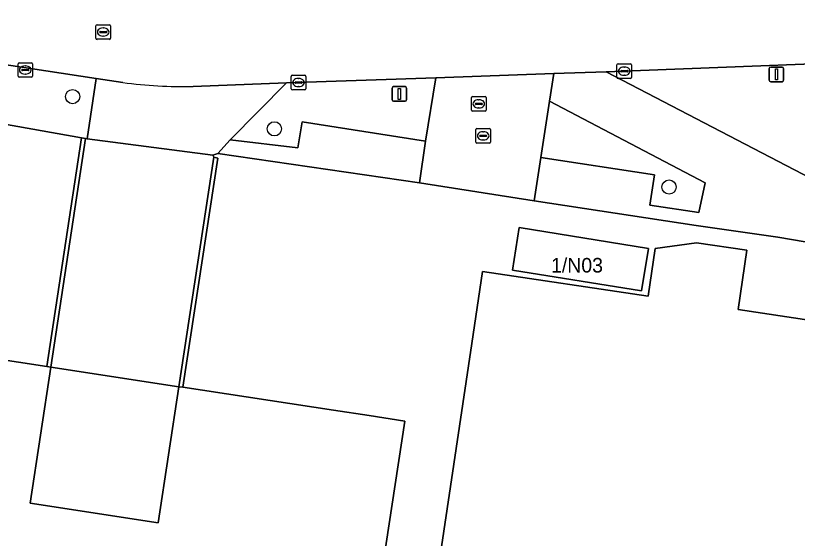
# Model space of a CAD drawing. Extents: x 163008 to 163854, y 382777 to 383982.
# Drawn here: x 163610.4 to 163664.1, y 382929.1 to 382965 of the extents above; entities that cross this region are included whole.
import ezdxf

# ---------------------------------------------------------------- set-up
doc = ezdxf.new("R2010")
doc.units = 0
for name, color, linetype in [('IMGEO_Berm_groen', 7, 'Continuous'), ('IMGEO_Boom', 7, 'Continuous'), ('IMGEO_Erf', 7, 'Continuous'), ('IMGEO_Groenvoorziening', 7, 'Continuous'), ('IMGEO_Kolk', 7, 'Continuous'), ('IMGEO_Lichtmast', 7, 'Continuous'), ('IMGEO_Muur', 7, 'Continuous'), ('IMGEO_Pand', 7, 'Continuous'), ('IMGEO_Pand_nummerreeks', 7, 'Continuous'), ('IMGEO_Pand_overbouw', 7, 'Continuous'), ('IMGEO_Rijbaan_lokaal_gesloten', 7, 'Continuous'), ('IMGEO_Rioolput', 7, 'Continuous'), ('IMGEO_Verkeersbordpaal', 7, 'Continuous'), ('IMGEO_Voetpad_open', 7, 'Continuous')]:
    doc.layers.add(name, color=color, linetype=linetype)

msp = doc.modelspace()

# ---------------------------------------------------------------- linework, layer by layer
at = {"layer": 'IMGEO_Berm_groen'}
msp.add_lwpolyline([(163639.301, 382960.692), (163629.051, 382960.332), (163625.178, 382956.437), (163629.814, 382955.872), (163630.123, 382957.675), (163638.596, 382956.331)], close=True, dxfattribs=at)
at = {"layer": 'IMGEO_Boom'}
for centre in [(163614.344, 382959.396), (163628.209, 382957.187), (163655.326, 382953.186)]:
    msp.add_circle(centre, 0.489, dxfattribs=at)
at = {"layer": 'IMGEO_Erf'}
for points in [[(163582.963, 382945.196), (163591.206, 382943.949), (163590.876, 382941.687), (163596.466, 382940.9), (163596.75, 382942.917), (163596.12, 382943.015), (163596.147, 382943.182), (163596.173, 382943.346), (163599.763, 382942.813), (163602.213, 382942.44), (163612.574, 382940.867), (163614.959, 382956.568), (163598.719, 382959.447), (163593.467, 382960.242), (163569.919, 382963.81)], [(163675.95, 382947.517), (163662.801, 382949.742), (163657.187, 382950.546), (163646.06, 382952.245), (163638.173, 382953.479), (163624.316, 382955.496), (163623.99, 382955.385), (163624.04, 382955.237), (163624.315, 382955.169), (163621.912, 382939.445), (163632.279, 382937.867), (163634.71, 382937.499), (163637.177, 382937.125), (163630.658, 382894.541)], [(163633.371, 382886.155), (163641.775, 382942.458), (163642.513, 382947.403), (163653.887, 382945.706), (163654.375, 382948.97), (163657.213, 382949.356), (163660.676, 382948.848), (163660.069, 382944.782), (163665.094, 382944.032)]]:
    msp.add_lwpolyline(points, dxfattribs=at)
msp.add_lwpolyline([(163653.443, 382946.065), (163644.566, 382947.492), (163645.035, 382950.407), (163653.912, 382948.979)], close=True, dxfattribs=at)
at = {"layer": 'IMGEO_Groenvoorziening'}
msp.add_lwpolyline([(163674.627, 382962.016), (163650.997, 382961.099), (163669.011, 382951.747), (163679.228, 382950.224)], dxfattribs=at)
msp.add_lwpolyline([(163647.115, 382959.08), (163646.511, 382955.211), (163654.325, 382954.019), (163654.013, 382951.942), (163657.373, 382951.433), (163657.804, 382953.488)], close=True, dxfattribs=at)
at = {"layer": 'IMGEO_Kolk'}
for p, q in [((163610.593, 382960.798), (163610.593, 382961.65)), ((163610.668, 382961.724), (163611.52, 382961.724)), ((163610.852, 382961.218), (163610.852, 382961.23)), ((163610.895, 382961.267), (163611.293, 382961.267)), ((163611.081, 382961.504), (163611.106, 382961.504)), ((163611.336, 382961.23), (163611.336, 382961.218)), ((163611.594, 382961.65), (163611.594, 382960.798)), ((163651.747, 382960.717), (163651.747, 382961.569)), ((163651.822, 382961.643), (163652.674, 382961.643)), ((163652.235, 382961.423), (163652.26, 382961.423)), ((163652.748, 382961.569), (163652.748, 382960.717)), ((163611.52, 382960.724), (163610.668, 382960.724)), ((163611.29, 382961.181), (163610.892, 382961.181)), ((163611.104, 382960.944), (163611.079, 382960.944)), ((163629.369, 382959.937), (163629.369, 382960.789)), ((163629.444, 382960.863), (163630.296, 382960.863)), ((163630.37, 382960.789), (163630.37, 382959.937)), ((163652.006, 382961.137), (163652.006, 382961.149)), ((163652.444, 382961.1), (163652.046, 382961.1)), ((163652.049, 382961.186), (163652.447, 382961.186)), ((163652.258, 382960.863), (163652.233, 382960.863)), ((163652.49, 382961.149), (163652.49, 382961.137)), ((163629.628, 382960.357), (163629.628, 382960.369)), ((163630.066, 382960.32), (163629.668, 382960.32)), ((163629.671, 382960.406), (163630.069, 382960.406)), ((163629.857, 382960.643), (163629.882, 382960.643)), ((163630.112, 382960.369), (163630.112, 382960.357)), ((163652.674, 382960.643), (163651.822, 382960.643)), ((163630.296, 382959.863), (163629.444, 382959.863)), ((163629.88, 382960.083), (163629.855, 382960.083)), ((163642.053, 382956.279), (163642.053, 382957.131)), ((163642.128, 382957.205), (163642.98, 382957.205)), ((163642.541, 382956.985), (163642.566, 382956.985)), ((163643.054, 382957.131), (163643.054, 382956.279)), ((163642.312, 382956.699), (163642.312, 382956.711)), ((163642.75, 382956.662), (163642.352, 382956.662)), ((163642.355, 382956.748), (163642.753, 382956.748)), ((163642.564, 382956.425), (163642.539, 382956.425)), ((163642.796, 382956.711), (163642.796, 382956.699)), ((163642.98, 382956.205), (163642.128, 382956.205))]:
    msp.add_line(p, q, dxfattribs=at)
for points in [[(163610.593, 382960.798), (163610.593, 382961.65)], [(163610.668, 382961.724), (163611.52, 382961.724)], [(163611.594, 382961.65), (163611.594, 382960.798)], [(163651.747, 382960.717), (163651.747, 382961.569)], [(163651.822, 382961.643), (163652.674, 382961.643)], [(163652.748, 382961.569), (163652.748, 382960.717)], [(163611.52, 382960.724), (163610.668, 382960.724)], [(163629.369, 382959.937), (163629.369, 382960.789)], [(163629.444, 382960.863), (163630.296, 382960.863)], [(163630.37, 382960.789), (163630.37, 382959.937)], [(163652.674, 382960.643), (163651.822, 382960.643)], [(163630.296, 382959.863), (163629.444, 382959.863)], [(163642.053, 382956.279), (163642.053, 382957.131)], [(163642.128, 382957.205), (163642.98, 382957.205)], [(163643.054, 382957.131), (163643.054, 382956.279)], [(163642.98, 382956.205), (163642.128, 382956.205)]]:
    msp.add_lwpolyline(points, dxfattribs=at)
for centre, radius, start, end in [((163610.67, 382961.648), 0.0765, 91.552, 178.448), ((163610.67, 382961.648), 0.0765, 91.552, 178.448), ((163610.892, 382961.227), 0.0403, 85.8775, 175.7526), ((163610.889, 382961.217), 0.0366, 178.938, 274.7102), ((163611.293, 382961.224), 0.043, 264.8664, 352.4533), ((163611.297, 382961.229), 0.0386, 1.7309, 96.639), ((163611.518, 382961.648), 0.0765, 1.552, 88.448), ((163611.518, 382961.648), 0.0765, 1.552, 88.448), ((163651.824, 382961.567), 0.0765, 91.552, 178.448), ((163651.824, 382961.567), 0.0765, 91.552, 178.448), ((163652.672, 382961.567), 0.0765, 1.552, 88.448), ((163652.672, 382961.567), 0.0765, 1.552, 88.448), ((163610.67, 382960.8), 0.0765, 181.552, 268.448), ((163610.67, 382960.8), 0.0765, 181.552, 268.448), ((163611.518, 382960.8), 0.0765, 271.552, 358.448), ((163611.518, 382960.8), 0.0765, 271.552, 358.448), ((163629.446, 382960.787), 0.0765, 91.552, 178.448), ((163629.446, 382960.787), 0.0765, 91.552, 178.448), ((163630.294, 382960.787), 0.0765, 1.552, 88.448), ((163630.294, 382960.787), 0.0765, 1.552, 88.448), ((163651.824, 382960.719), 0.0765, 181.552, 268.448), ((163651.824, 382960.719), 0.0765, 181.552, 268.448), ((163652.046, 382961.146), 0.0403, 85.8775, 175.7526), ((163652.043, 382961.136), 0.0366, 178.938, 274.7102), ((163652.447, 382961.143), 0.043, 264.8664, 352.4533), ((163652.451, 382961.148), 0.0386, 1.7309, 96.639), ((163652.672, 382960.719), 0.0765, 271.552, 358.448), ((163652.672, 382960.719), 0.0765, 271.552, 358.448), ((163629.668, 382960.366), 0.0403, 85.8775, 175.7526), ((163629.665, 382960.356), 0.0366, 178.938, 274.7102), ((163630.069, 382960.363), 0.043, 264.8664, 352.4533), ((163630.073, 382960.368), 0.0386, 1.7309, 96.639), ((163629.446, 382959.939), 0.0765, 181.552, 268.448), ((163629.446, 382959.939), 0.0765, 181.552, 268.448), ((163630.294, 382959.939), 0.0765, 271.552, 358.448), ((163630.294, 382959.939), 0.0765, 271.552, 358.448), ((163642.13, 382957.129), 0.0765, 91.552, 178.448), ((163642.13, 382957.129), 0.0765, 91.552, 178.448), ((163642.978, 382957.129), 0.0765, 1.552, 88.448), ((163642.978, 382957.129), 0.0765, 1.552, 88.448), ((163642.352, 382956.708), 0.0403, 85.8775, 175.7526), ((163642.349, 382956.698), 0.0366, 178.938, 274.7102), ((163642.753, 382956.705), 0.043, 264.8664, 352.4533), ((163642.757, 382956.71), 0.0386, 1.7309, 96.639), ((163642.13, 382956.281), 0.0765, 181.552, 268.448), ((163642.13, 382956.281), 0.0765, 181.552, 268.448), ((163642.978, 382956.281), 0.0765, 271.552, 358.448), ((163642.978, 382956.281), 0.0765, 271.552, 358.448)]:
    msp.add_arc(centre, radius, start, end, dxfattribs=at)
for centre, major_axis, ratio, start_param, end_param in [((163611.08, 382961.224), (-0.387, 0.002), 0.722429, 4.712389, 7.853982), ((163611.105, 382961.224), (-0.39, 0.002), 0.717154, 1.570796, 4.712389), ((163652.234, 382961.143), (-0.387, 0.002), 0.722429, 4.712389, 7.853982), ((163652.259, 382961.143), (-0.39, 0.002), 0.717154, 1.570796, 4.712389), ((163629.856, 382960.363), (-0.387, 0.002), 0.722429, 4.712389, 7.853982), ((163629.881, 382960.363), (-0.39, 0.002), 0.717154, 1.570796, 4.712389), ((163642.54, 382956.705), (-0.387, 0.002), 0.722429, 4.712389, 7.853982), ((163642.565, 382956.705), (-0.39, 0.002), 0.717154, 1.570796, 4.712389)]:
    msp.add_ellipse(centre, major_axis=major_axis, ratio=ratio, start_param=start_param, end_param=end_param, dxfattribs=at)
at = {"layer": 'IMGEO_Lichtmast'}
for p, q in [((163662.209, 382960.522), (163662.209, 382961.322)), ((163662.209, 382961.322), (163662.209, 382960.522)), ((163662.309, 382961.422), (163663.099, 382961.422)), ((163663.099, 382961.422), (163662.309, 382961.422)), ((163663.199, 382961.322), (163663.199, 382960.522)), ((163663.199, 382960.522), (163663.199, 382961.322)), ((163663.099, 382960.422), (163662.309, 382960.422)), ((163662.309, 382960.422), (163663.099, 382960.422))]:
    msp.add_line(p, q, dxfattribs=at)
msp.add_lwpolyline([(163662.629, 382961.297), (163662.779, 382961.297), (163662.779, 382960.547), (163662.629, 382960.547), (163662.629, 382961.297)], dxfattribs=at)
for centre, start, end in [((163662.309, 382961.322), 90, 180), ((163662.309, 382961.322), 90, 180), ((163663.099, 382961.322), 0, 90), ((163663.099, 382961.322), 360, 90), ((163662.309, 382960.522), 180, 270), ((163662.309, 382960.522), 180, 270), ((163663.099, 382960.522), 270, 0), ((163663.099, 382960.522), 270, 0)]:
    msp.add_arc(centre, 0.1, start, end, dxfattribs=at)
at = {"layer": 'IMGEO_Muur'}
for points in [[(163614.959, 382956.568), (163612.574, 382940.867), (163612.842, 382940.823), (163615.226, 382956.521)], [(163624.315, 382955.169), (163624.04, 382955.237), (163621.646, 382939.485), (163621.912, 382939.445)]]:
    msp.add_lwpolyline(points, close=True, dxfattribs=at)
at = {"layer": 'IMGEO_Pand'}
msp.add_lwpolyline([(163653.443, 382946.065), (163653.912, 382948.979), (163645.035, 382950.407), (163644.566, 382947.492)], close=True, dxfattribs=at)
for points in [[(163686.07, 382880.075), (163694.944, 382939.641), (163675.573, 382942.478), (163671.874, 382943.02), (163665.094, 382944.032), (163660.069, 382944.782), (163660.676, 382948.848), (163657.213, 382949.356), (163654.375, 382948.97), (163653.887, 382945.706), (163642.513, 382947.403), (163641.775, 382942.458), (163633.371, 382886.155), (163632.813, 382886.325), (163623.367, 382823.699)], [(163630.658, 382894.541), (163637.177, 382937.125), (163634.71, 382937.499), (163632.279, 382937.867), (163621.912, 382939.445), (163621.646, 382939.485), (163620.226, 382930.143), (163611.422, 382931.48), (163612.842, 382940.823), (163612.574, 382940.867), (163602.213, 382942.44), (163599.763, 382942.813), (163596.173, 382943.346), (163596.147, 382943.182), (163596.12, 382943.015), (163596.75, 382942.917), (163596.466, 382940.9), (163590.876, 382941.687), (163591.206, 382943.949), (163582.963, 382945.196)]]:
    msp.add_lwpolyline(points, dxfattribs=at)
at = {"layer": 'IMGEO_Pand_overbouw'}
msp.add_lwpolyline([(163612.842, 382940.823), (163611.422, 382931.48), (163620.226, 382930.143), (163621.646, 382939.485)], close=True, dxfattribs=at)
at = {"layer": 'IMGEO_Rijbaan_lokaal_gesloten'}
for points in [[(163292.545, 383009.569), (163296.84, 383008.817), (163304.96, 383007.61), (163321.045, 383005.203), (163329.509, 383003.951), (163334.952, 383003.075), (163339.568, 383002.444), (163411.931, 382991.584), (163416.286, 382990.97), (163423.758, 382989.792), (163438.655, 382987.556), (163481.173, 382981.103), (163506.122, 382977.311), (163550.446, 382970.596), (163562.809, 382968.717), (163570.543, 382967.542), (163594.132, 382963.957), (163599.415, 382963.154), (163615.953, 382960.64), (163617.8, 382960.359)], [(163622.627, 382960.091), (163629.051, 382960.332), (163639.301, 382960.692), (163647.404, 382960.974), (163650.997, 382961.099), (163674.627, 382962.016), (163676.656, 382962.06)]]:
    msp.add_lwpolyline(points, dxfattribs=at)
for points in [[(163624.04, 382955.237), (163623.99, 382955.385), (163615.342, 382956.5), (163615.226, 382956.521), (163612.842, 382940.823), (163621.646, 382939.485)], [(163612.842, 382940.823), (163611.422, 382931.48), (163620.226, 382930.143), (163621.646, 382939.485)]]:
    msp.add_lwpolyline(points, close=True, dxfattribs=at)
msp.add_arc((163622.092, 382994.054), 33.967, 262.7414, 270.9029, dxfattribs=at)
at = {"layer": 'IMGEO_Rioolput'}
for p, q in [((163615.946, 382963.403), (163615.946, 382964.255)), ((163616.021, 382964.329), (163616.873, 382964.329)), ((163616.434, 382964.109), (163616.459, 382964.109)), ((163616.947, 382964.255), (163616.947, 382963.403)), ((163616.205, 382963.823), (163616.205, 382963.835)), ((163616.643, 382963.786), (163616.245, 382963.786)), ((163616.248, 382963.872), (163616.646, 382963.872)), ((163616.457, 382963.549), (163616.432, 382963.549)), ((163616.689, 382963.835), (163616.689, 382963.823)), ((163616.873, 382963.329), (163616.021, 382963.329)), ((163641.754, 382958.474), (163641.754, 382959.326)), ((163641.829, 382959.4), (163642.681, 382959.4)), ((163642.242, 382959.18), (163642.267, 382959.18)), ((163642.755, 382959.326), (163642.755, 382958.474)), ((163642.013, 382958.894), (163642.013, 382958.906)), ((163642.451, 382958.857), (163642.053, 382958.857)), ((163642.056, 382958.943), (163642.454, 382958.943)), ((163642.265, 382958.62), (163642.24, 382958.62)), ((163642.497, 382958.906), (163642.497, 382958.894)), ((163642.681, 382958.4), (163641.829, 382958.4))]:
    msp.add_line(p, q, dxfattribs=at)
for points in [[(163615.946, 382963.403), (163615.946, 382964.255)], [(163616.021, 382964.329), (163616.873, 382964.329)], [(163616.947, 382964.255), (163616.947, 382963.403)], [(163616.873, 382963.329), (163616.021, 382963.329)], [(163641.754, 382958.474), (163641.754, 382959.326)], [(163641.829, 382959.4), (163642.681, 382959.4)], [(163642.755, 382959.326), (163642.755, 382958.474)], [(163642.681, 382958.4), (163641.829, 382958.4)]]:
    msp.add_lwpolyline(points, dxfattribs=at)
for centre, radius, start, end in [((163616.023, 382964.253), 0.0765, 91.552, 178.448), ((163616.023, 382964.253), 0.0765, 91.552, 178.448), ((163616.871, 382964.253), 0.0765, 1.552, 88.448), ((163616.871, 382964.253), 0.0765, 1.552, 88.448), ((163616.023, 382963.405), 0.0765, 181.552, 268.448), ((163616.023, 382963.405), 0.0765, 181.552, 268.448), ((163616.245, 382963.832), 0.0403, 85.8775, 175.7526), ((163616.242, 382963.822), 0.0366, 178.938, 274.7102), ((163616.646, 382963.829), 0.043, 264.8664, 352.4533), ((163616.65, 382963.834), 0.0386, 1.7309, 96.639), ((163616.871, 382963.405), 0.0765, 271.552, 358.448), ((163616.871, 382963.405), 0.0765, 271.552, 358.448), ((163641.831, 382959.324), 0.0765, 91.552, 178.448), ((163641.831, 382959.324), 0.0765, 91.552, 178.448), ((163642.679, 382959.324), 0.0765, 1.552, 88.448), ((163642.679, 382959.324), 0.0765, 1.552, 88.448), ((163642.053, 382958.903), 0.0403, 85.8775, 175.7526), ((163642.05, 382958.893), 0.0366, 178.938, 274.7102), ((163642.454, 382958.9), 0.043, 264.8664, 352.4533), ((163642.458, 382958.905), 0.0386, 1.7309, 96.639), ((163641.831, 382958.476), 0.0765, 181.552, 268.448), ((163641.831, 382958.476), 0.0765, 181.552, 268.448), ((163642.679, 382958.476), 0.0765, 271.552, 358.448), ((163642.679, 382958.476), 0.0765, 271.552, 358.448)]:
    msp.add_arc(centre, radius, start, end, dxfattribs=at)
for centre, major_axis, ratio, start_param, end_param in [((163616.433, 382963.829), (-0.387, 0.002), 0.722429, 4.712389, 7.853982), ((163616.458, 382963.829), (-0.39, 0.002), 0.717154, 1.570796, 4.712389), ((163642.241, 382958.9), (-0.387, 0.002), 0.722429, 4.712389, 7.853982), ((163642.266, 382958.9), (-0.39, 0.002), 0.717154, 1.570796, 4.712389)]:
    msp.add_ellipse(centre, major_axis=major_axis, ratio=ratio, start_param=start_param, end_param=end_param, dxfattribs=at)
at = {"layer": 'IMGEO_Verkeersbordpaal'}
for p, q in [((163636.301, 382959.185), (163636.301, 382959.985)), ((163636.301, 382959.985), (163636.301, 382959.185)), ((163636.401, 382960.085), (163637.191, 382960.085)), ((163637.191, 382960.085), (163636.401, 382960.085)), ((163637.291, 382959.985), (163637.291, 382959.185)), ((163637.291, 382959.185), (163637.291, 382959.985)), ((163637.191, 382959.085), (163636.401, 382959.085)), ((163636.401, 382959.085), (163637.191, 382959.085))]:
    msp.add_line(p, q, dxfattribs=at)
msp.add_lwpolyline([(163636.721, 382959.96), (163636.871, 382959.96), (163636.871, 382959.21), (163636.721, 382959.21), (163636.721, 382959.96)], dxfattribs=at)
for centre, start, end in [((163636.401, 382959.985), 90, 180), ((163636.401, 382959.985), 90, 180), ((163637.191, 382959.985), 0, 90), ((163637.191, 382959.985), 360, 90), ((163636.401, 382959.185), 180, 270), ((163636.401, 382959.185), 180, 270), ((163637.191, 382959.185), 270, 0), ((163637.191, 382959.185), 270, 0)]:
    msp.add_arc(centre, 0.1, start, end, dxfattribs=at)
at = {"layer": 'IMGEO_Voetpad_open'}
for points in [[(163615.226, 382956.521), (163615.342, 382956.5), (163615.953, 382960.64), (163599.415, 382963.154), (163598.719, 382959.447), (163614.959, 382956.568)], [(163647.115, 382959.08), (163647.404, 382960.974), (163639.301, 382960.692), (163638.596, 382956.331), (163638.173, 382953.479), (163646.06, 382952.245), (163646.511, 382955.211)], [(163638.596, 382956.331), (163630.123, 382957.675), (163629.814, 382955.872), (163625.178, 382956.437), (163624.316, 382955.496), (163638.173, 382953.479)]]:
    msp.add_lwpolyline(points, close=True, dxfattribs=at)
for points in [[(163679.228, 382950.224), (163669.011, 382951.747), (163650.997, 382961.099), (163647.404, 382960.974), (163647.115, 382959.08), (163657.804, 382953.488), (163657.373, 382951.433), (163654.013, 382951.942), (163654.325, 382954.019), (163646.511, 382955.211), (163646.06, 382952.245), (163657.187, 382950.546), (163662.801, 382949.742), (163675.95, 382947.517), (163675.573, 382942.478), (163694.944, 382939.641), (163696.771, 382939.336), (163697.597, 382939.219)], [(163617.8, 382960.359), (163615.953, 382960.64), (163615.342, 382956.5), (163623.99, 382955.385), (163624.316, 382955.496), (163625.178, 382956.437), (163629.051, 382960.332), (163622.627, 382960.091)]]:
    msp.add_lwpolyline(points, dxfattribs=at)
msp.add_arc((163622.092, 382994.054), 33.967, 262.7414, 270.9029, dxfattribs=at)

# ---------------------------------------------------------------- texts
at = {"layer": 'IMGEO_Pand_nummerreeks'}
msp.add_text('1/N03', height=1, dxfattribs=at).set_placement((163647.217, 382947.322))

doc.saveas('drawing.dxf')
